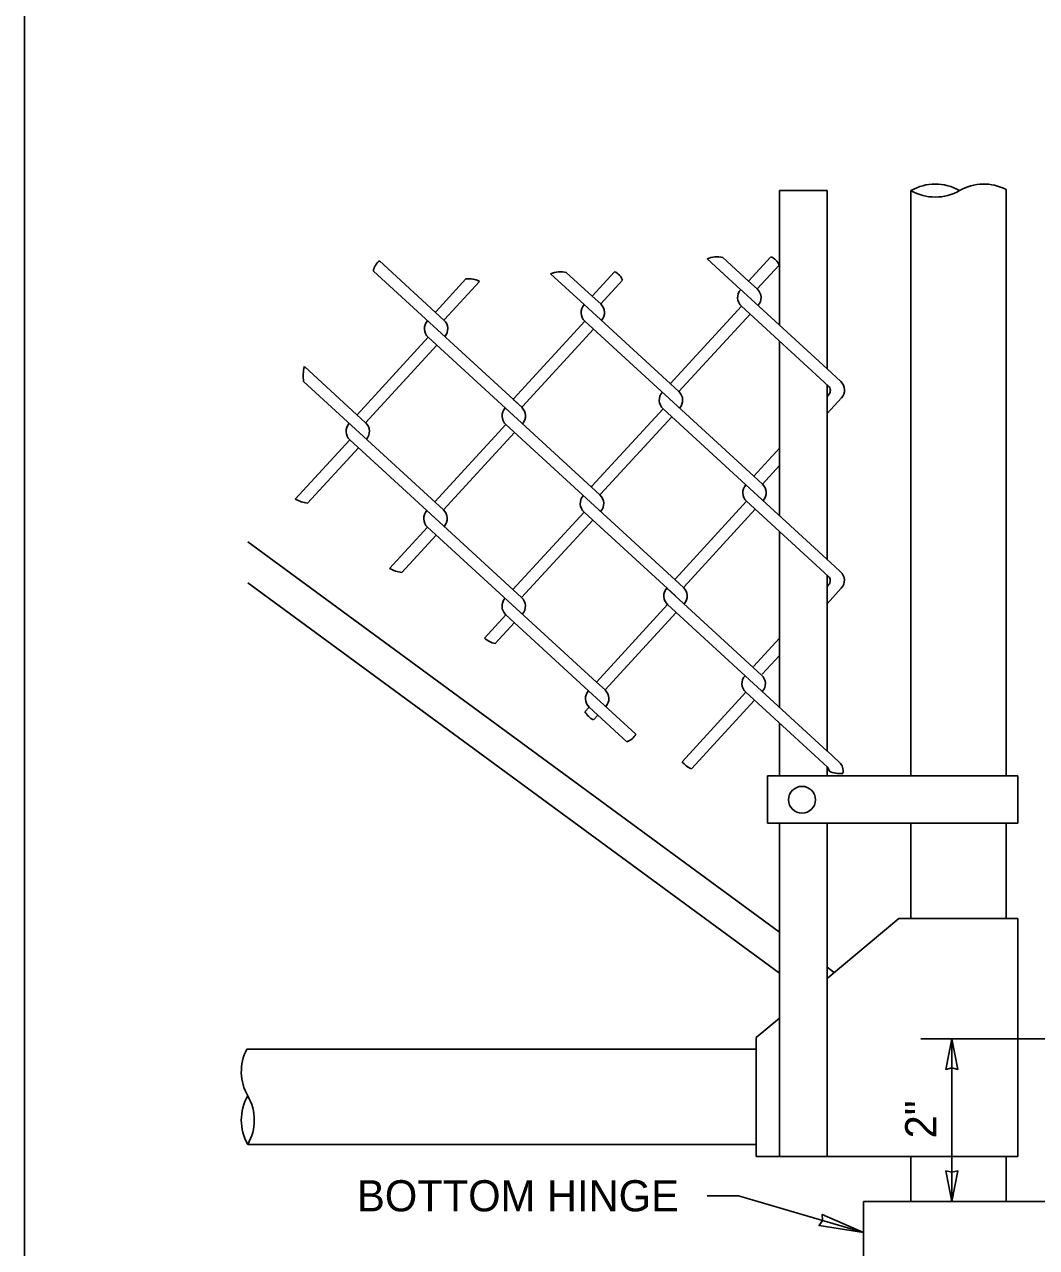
# Model space of a CAD drawing. Extents: x 99862 to 104211, y 98939 to 105076.
# Drawn here: x 99862 to 100382, y 103475 to 104103 of the extents above; entities that cross this region are included whole.
import ezdxf

# ---------------------------------------------------------------- set-up
doc = ezdxf.new("R2010")
doc.units = 0
for name, color, linetype in [('Level 1', 7, 'Continuous'), ('Level 15', 7, 'Continuous'), ('Level 20', 7, 'Continuous'), ('Level 4', 7, 'Continuous'), ('Level 7', 7, 'Continuous')]:
    doc.layers.add(name, color=color, linetype=linetype)

msp = doc.modelspace()

# ---------------------------------------------------------------- linework, layer by layer
at = {"layer": 'Level 1'}
msp.add_lwpolyline([(99862, 102999.5), (103151, 102999.5), (103151, 105075.5), (99862, 105075.5)], close=True, dxfattribs=at)
at = {"layer": 'Level 15'}
for p, q in [((100430.77, 103582.48), (100322.08, 103582.48)), ((100338.08, 103582.48), (100338.08, 103498.91)), ((100228.53, 103501.87), (100212.53, 103501.87)), ((100292.63, 103483.03), (100228.53, 103501.87))]:
    msp.add_line(p, q, dxfattribs=at)
for points in [[(100338.08, 103582.48), (100335, 103566.75), (100338.08, 103567.48), (100341.16, 103566.75)], [(100338.08, 103498.91), (100335, 103514.64), (100338.08, 103513.91), (100341.16, 103514.64)], [(100292.63, 103483.03), (100269.89, 103486.6), (100271.74, 103489.17), (100271.57, 103492.33)]]:
    msp.add_lwpolyline(points, close=True, dxfattribs=at)
at = {"layer": 'Level 4'}
for p, q in [((100044.28, 103981.81), (100077.34, 103951.47)), ((100212.46, 103982.86), (100229.68, 103967.06)), ((100220.52, 103983.61), (100233.73, 103971.48)), ((100245.22, 103984), (100233.73, 103971.48)), ((100249.4, 103979.67), (100238.15, 103967.42)), ((100041.12, 103976.57), (100117.25, 103906.69)), ((100132.1, 103975.18), (100149.32, 103959.38)), ((100140.16, 103975.93), (100153.38, 103963.8)), ((100164.86, 103976.31), (100153.38, 103963.8)), ((100088.56, 103972.56), (100073.26, 103955.89)), ((100095.59, 103971.35), (100077.68, 103951.83)), ((100169.04, 103971.99), (100157.8, 103959.74)), ((100228.9, 103967.77), (100273.98, 103926.39)), ((100233.73, 103971.48), (100238.15, 103967.42)), ((100153.38, 103963.8), (100157.8, 103959.74)), ((100073.26, 103955.89), (100072.92, 103955.52)), ((100149.32, 103959.38), (100197.94, 103914.74)), ((100230.04, 103958.58), (100193.52, 103918.8)), ((100234.46, 103954.53), (100197.94, 103914.74)), ((100230.04, 103958.58), (100274.74, 103917.55)), ((100077.68, 103951.83), (100077.34, 103951.47)), ((100149.68, 103950.9), (100113.17, 103911.12)), ((100149.68, 103950.9), (100236.37, 103871.32)), ((100158.16, 103951.26), (100158.16, 103951.26)), ((100069.23, 103942.63), (100032.71, 103902.84)), ((100069.23, 103942.63), (100113.19, 103902.27)), ((100077.71, 103942.99), (100077.71, 103942.99)), ((100154.1, 103946.84), (100117.59, 103907.06)), ((100073.65, 103938.57), (100037.13, 103898.79)), ((100005.7, 103927.64), (100037.13, 103898.79)), ((100273.98, 103926.39), (100281.01, 103919.94)), ((100005.3, 103919.86), (100077.04, 103854.01)), ((100113.17, 103911.12), (100112.83, 103910.75)), ((100112.83, 103910.75), (100117.25, 103906.69)), ((100274.92, 103913.31), (100273.98, 103912.29)), ((100281.37, 103911.47), (100273.98, 103903.42)), ((100108.77, 103906.33), (100157.39, 103861.7)), ((100117.59, 103907.06), (100117.25, 103906.69)), ((100189.83, 103905.9), (100153.31, 103866.12)), ((100189.83, 103905.9), (100232.32, 103866.9)), ((100198.3, 103906.27), (100198.3, 103906.27)), ((100117.61, 103898.21), (100117.61, 103898.21)), ((100194.25, 103901.85), (100157.73, 103862.07)), ((100109.13, 103897.85), (100072.62, 103858.07)), ((100113.55, 103893.79), (100077.04, 103854.01)), ((100109.13, 103897.85), (100200.25, 103814.22)), ((100029.02, 103889.95), (100001.04, 103859.47)), ((100033.44, 103885.89), (100007.3, 103857.42)), ((100029.02, 103889.95), (100068.56, 103853.65)), ((100037.5, 103890.31), (100037.5, 103890.31)), ((100249.55, 103885.68), (100236.37, 103871.32)), ((100249.55, 103876.8), (100240.79, 103867.26)), ((100232.32, 103866.9), (100277.93, 103825.03)), ((100236.37, 103871.32), (100240.79, 103867.26)), ((100153.31, 103866.12), (100152.97, 103865.75)), ((100157.73, 103862.07), (100157.39, 103861.7)), ((100232.68, 103858.42), (100196.16, 103818.64)), ((100237.1, 103854.37), (100200.58, 103814.59)), ((100232.68, 103858.42), (100274.67, 103819.88)), ((100068.56, 103853.65), (100117.18, 103809.02)), ((100149.28, 103852.86), (100112.76, 103813.08)), ((100153.7, 103848.8), (100117.18, 103809.02)), ((100149.28, 103852.86), (100196.19, 103809.8)), ((100157.76, 103853.22), (100157.76, 103853.22)), ((100068.92, 103845.17), (100049.43, 103823.93)), ((100068.92, 103845.17), (100155.61, 103765.6)), ((100077.4, 103845.53), (100077.4, 103845.53)), ((100073.34, 103841.11), (100055.69, 103821.88)), ((100277.93, 103825.03), (100280.94, 103822.27)), ((100196.16, 103818.64), (100195.83, 103818.27)), ((100195.83, 103818.27), (100200.25, 103814.22)), ((100191.77, 103813.85), (100240.39, 103769.22)), ((100274.85, 103815.64), (100273.98, 103814.69)), ((100281.3, 103813.79), (100273.98, 103805.82)), ((100192.13, 103805.38), (100155.61, 103765.6)), ((100192.13, 103805.38), (100274.04, 103730.19)), ((100109.07, 103800.18), (100098.07, 103788.2)), ((100109.07, 103800.18), (100151.56, 103761.18)), ((100196.55, 103801.32), (100160.03, 103761.54)), ((100113.49, 103796.12), (100103.64, 103785.39)), ((100249.55, 103788.08), (100236.31, 103773.65)), ((100249.55, 103779.2), (100240.73, 103769.59)), ((100151.56, 103761.18), (100175.87, 103738.86)), ((100155.61, 103765.6), (100160.04, 103761.54)), ((100232.28, 103760.38), (100199.56, 103724.74)), ((100232.28, 103760.38), (100274.03, 103722.06)), ((100240.75, 103760.75), (100240.75, 103760.75)), ((100236.7, 103756.33), (100204.33, 103721.07)), ((100151.92, 103752.7), (100149.7, 103750.28)), ((100151.92, 103752.7), (100171.22, 103734.98)), ((100156.34, 103748.64), (100154.05, 103746.15)), ((100160.4, 103753.06), (100160.4, 103753.06)), ((100273.98, 103730.25), (100280.3, 103724.45))]:
    msp.add_line(p, q, dxfattribs=at)
for centre, radius, start, end in [((100048.35, 103975.78), 7.28, 124.03277, 173.76719), ((100217.53, 103971.99), 12, 75.59976, 115.00143), ((100242.23, 103976.93), 7.68, 20.96983, 67.06574), ((100137.18, 103964.3), 12, 75.59976, 115.00143), ((100161.87, 103969.24), 7.68, 20.96983, 67.06574), ((100090.12, 103960.66), 12, 62.898, 97.46571), ((100234.1, 103963), 6, 137.45049, 227.45049), ((100234.1, 103963), 6, 317.45049, 47.45049), ((100153.74, 103955.32), 6, 137.45049, 227.45049), ((100153.74, 103955.32), 6, 317.45049, 47.45049), ((100073.29, 103947.05), 6, 137.45049, 227.45049), ((100073.29, 103947.05), 6, 317.45049, 47.45049), ((100023.85, 103922.8), 18.78, 165.08809, 189.01698), ((100272.71, 103915.34), 3, 317.45049, 47.45074), ((100276.95, 103915.52), 6, 317.45049, 47.45049), ((100193.88, 103910.32), 6, 137.45049, 227.45049), ((100193.88, 103910.32), 6, 317.45049, 47.45049), ((100113.19, 103902.27), 6, 137.45049, 227.45049), ((100113.19, 103902.27), 6, 317.45049, 47.45049), ((100033.08, 103894.37), 6, 137.45049, 227.45049), ((100033.08, 103894.37), 6, 317.45049, 47.45049), ((100236.74, 103862.84), 6, 137.45049, 227.45049), ((100236.74, 103862.84), 6, 317.45049, 47.45049), ((100153.34, 103857.28), 6, 137.45049, 227.45049), ((100153.34, 103857.28), 6, 317.45049, 47.45049), ((100009.92, 103876.02), 18.78, 241.77586, 261.98348), ((100072.98, 103849.59), 6, 317.45049, 47.45049), ((100072.98, 103849.59), 6, 137.45049, 227.45049), ((100058.31, 103840.48), 18.78, 241.77586, 261.98348), ((100272.64, 103817.67), 3, 317.45049, 47.4511), ((100276.88, 103817.85), 6, 317.45049, 47.45049), ((100196.19, 103809.8), 6, 137.45049, 227.45049), ((100196.19, 103809.8), 6, 317.45049, 47.45049), ((100113.13, 103804.6), 6, 137.45049, 227.45049), ((100113.13, 103804.6), 6, 317.45049, 47.45049), ((100106.75, 103798.44), 13.42, 229.74322, 256.60019), ((100236.33, 103764.8), 6, 137.45049, 227.45049), ((100236.33, 103764.8), 6, 317.45049, 47.45049), ((100155.98, 103757.12), 6, 137.45049, 227.45049), ((100155.98, 103757.12), 6, 317.45049, 47.45049), ((100160.89, 103757.69), 13.42, 213.51997, 239.35862), ((100168.46, 103743.01), 8.49, 289.02128, 330.77363), ((100209.01, 103732.09), 11.97, 217.85376, 246.99627), ((100276.24, 103720.03), 6, 347.64649, 47.45049), ((100272, 103719.85), 3, 2.45083, 47.45117), ((100280.5, 103730.61), 11.97, 242.64638, 277.69542)]:
    msp.add_arc(centre, radius, start, end, dxfattribs=at)
at = {"layer": 'Level 7'}
for p, q in [((100273.98, 104017.94), (100249.55, 104017.94)), ((100249.55, 103948.82), (100249.55, 104017.94)), ((100273.98, 103926.39), (100273.98, 104017.94)), ((100317.06, 103717.55), (100317.06, 104017.94)), ((100365.92, 103717.55), (100365.92, 104018.5)), ((100249.55, 103851.08), (100249.55, 103940.67)), ((100273.98, 103828.66), (100273.98, 103918.25)), ((100249.55, 103752.67), (100249.55, 103842.94)), ((100249.55, 103637.25), (99976.65, 103837.68)), ((100249.55, 103616.08), (99976.65, 103816.51)), ((100273.98, 103730.25), (100273.98, 103820.52)), ((100249.55, 103717.55), (100249.55, 103744.53)), ((100371.99, 103717.55), (100243.48, 103717.55)), ((100243.48, 103717.55), (100243.48, 103693.12)), ((100273.98, 103717.55), (100273.98, 103722.1)), ((100371.99, 103717.55), (100371.99, 103693.12)), ((100371.99, 103693.12), (100243.48, 103693.12)), ((100249.55, 103522.12), (100249.55, 103693.12)), ((100273.98, 103522.12), (100273.98, 103693.12)), ((100317.06, 103644.26), (100317.06, 103693.12)), ((100365.92, 103644.26), (100365.92, 103693.12)), ((100310.92, 103644.26), (100273.98, 103613.48)), ((100310.92, 103644.26), (100371.99, 103644.26)), ((100371.99, 103522.12), (100371.99, 103644.26)), ((100277.7, 103616.58), (100273.98, 103619.31)), ((100249.55, 103593.12), (100237.63, 103583.19)), ((100237.63, 103522.12), (100237.63, 103583.19)), ((99976.09, 103577.08), (100237.63, 103577.08)), ((99976.65, 103528.23), (100237.63, 103528.23)), ((100237.63, 103522.12), (100371.99, 103522.12)), ((100317.06, 103522.12), (100317.06, 103498.91)), ((100365.92, 103522.12), (100365.92, 103498.91)), ((100292.63, 103498.91), (100292.63, 103467.16)), ((100292.63, 103498.91), (100507.6, 103498.91))]:
    msp.add_line(p, q, dxfattribs=at)
msp.add_circle((100261.12, 103705.17), 6.89, dxfattribs=at)
for centre, start, end in [((100329.53, 103996.34), 60, 120), ((100329.53, 104039.54), 240, 300), ((100354.47, 103996.34), 62.66504, 120), ((99998.25, 103565.63), 152.66504, 210), ((99998.25, 103540.7), 150, 210), ((99955.05, 103540.7), 330, 30)]:
    msp.add_arc(centre, 24.94, start, end, dxfattribs=at)

# ---------------------------------------------------------------- texts
at = {"layer": 'Level 20'}
for s, rotation, p in [('2"', 90, (100330.08, 103531.33)), ('BOTTOM HINGE', 360, (100032.72, 103493.87))]:
    msp.add_text(s, height=16, rotation=rotation, dxfattribs=at).set_placement(p)

doc.saveas('drawing.dxf')
